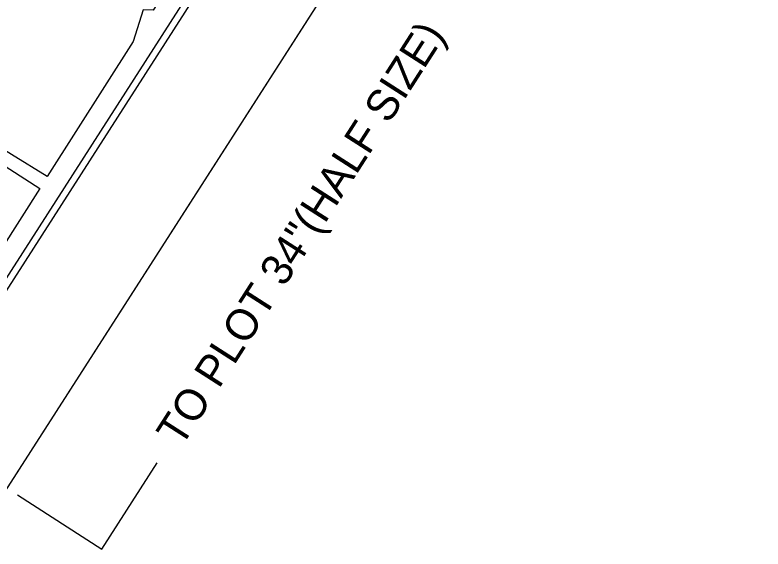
# Model space of a CAD drawing. Extents: x 2346049 to 2349719, y 842061 to 846435.
# Drawn here: x 2347924 to 2349719, y 842061 to 843342 of the extents above; entities that cross this region are included whole.
import ezdxf

# ---------------------------------------------------------------- set-up
doc = ezdxf.new("R2010")
doc.units = 0
for name, color, linetype in [('Prop DSN Text', 7, 'Continuous'), ('Scratch_Level_0', 7, 'Continuous'), ('Sheet Cutting Line CELL', 7, 'Continuous'), ('Sheet Detail CELL', 7, 'Continuous'), ('Sheet Plot Border Inside CELL', 7, 'Continuous'), ('Sheet Plot Border Outside CELL', 7, 'Continuous')]:
    doc.layers.add(name, color=color, linetype=linetype)

msp = doc.modelspace()

# ---------------------------------------------------------------- linework, layer by layer
at = {"layer": 'Prop DSN Text'}
msp.add_lwpolyline([(2347685.9, 842805.1), (2347827.5, 843026), (2347983.9, 842925.8), (2347842.2, 842704.9)], close=True, dxfattribs=at)
at = {"layer": 'Scratch_Level_0'}
for points in [[(2349350.4, 845074.8), (2348851.8, 844297.2), (2348757.8, 844341), (2348462.4, 843706.5), (2348375.3, 843541.3), (2348255.5, 843353.8), (2348231.9, 843354.7), (2348207.8, 843279), (2348000.9, 842955.2), (2347829, 843060.7), (2347638.3, 842833.8), (2347080.7, 843191.4), (2347008.6, 843443.9), (2347324.8, 843936.9), (2346937.8, 844263.6), (2347160.2, 844610.4)], [(2349350.4, 845074.8), (2348851.8, 844297.2), (2348757.8, 844341), (2348462.4, 843706.5), (2348375.3, 843541.3), (2348255.5, 843353.8), (2348231.9, 843354.7), (2348207.8, 843279), (2348000.9, 842955.2), (2347829, 843060.7), (2347638.3, 842833.8), (2347080.7, 843191.4), (2347008.6, 843443.9), (2347324.8, 843936.9), (2346961.1, 844244), (2347005, 844312.5), (2347188.2, 844598.2)], [(2349350.4, 845074.8), (2348851.8, 844297.2), (2348757.8, 844341), (2348462.4, 843706.5), (2348375.3, 843541.3), (2348255.5, 843353.8), (2348231.9, 843354.7), (2348207.8, 843279), (2348000.9, 842955.2), (2347829, 843060.7), (2347638.3, 842833.8), (2347080.7, 843191.4), (2347008.6, 843443.9), (2347324.8, 843936.9), (2346961.1, 844244), (2347005, 844312.5), (2347188.2, 844598.2)]]:
    msp.add_lwpolyline(points, dxfattribs=at)
at = {"layer": 'Sheet Cutting Line CELL'}
msp.add_line((2347900.5, 842198.8), (2349718.7, 845033.9), dxfattribs=at)
msp.add_line((2347900.5, 842198.8), (2349718.7, 845033.9), dxfattribs=at)
at = {"layer": 'Sheet Detail CELL'}
for p, q in [((2348132.7, 842061.1), (2348265.3, 842267.8)), ((2347930, 842191.1), (2348132.7, 842061.1))]:
    msp.add_line(p, q, dxfattribs=at)
msp.add_lwpolyline([(2346465.3, 843526.7), (2348084.7, 846052), (2349473.7, 845161.3), (2347854.2, 842636)], close=True, dxfattribs=at)
at = {"layer": 'Sheet Plot Border Inside CELL'}
msp.add_lwpolyline([(2348083.9, 846082.3), (2346302.5, 843304.4), (2347720, 842395.3), (2349501.5, 845173.2)], close=True, dxfattribs=at)
at = {"layer": 'Sheet Plot Border Outside CELL'}
msp.add_lwpolyline([(2347866.8, 846221.5), (2346048.7, 843386.4), (2347900.5, 842198.8), (2349718.7, 845033.9)], close=True, dxfattribs=at)

# ---------------------------------------------------------------- texts
at = {"layer": 'Sheet Detail CELL'}
msp.add_text('TO PLOT 34"(HALF SIZE)', height=75, rotation=57.3281, dxfattribs=at).set_placement((2348322.9, 842302.9))

doc.saveas('drawing.dxf')
